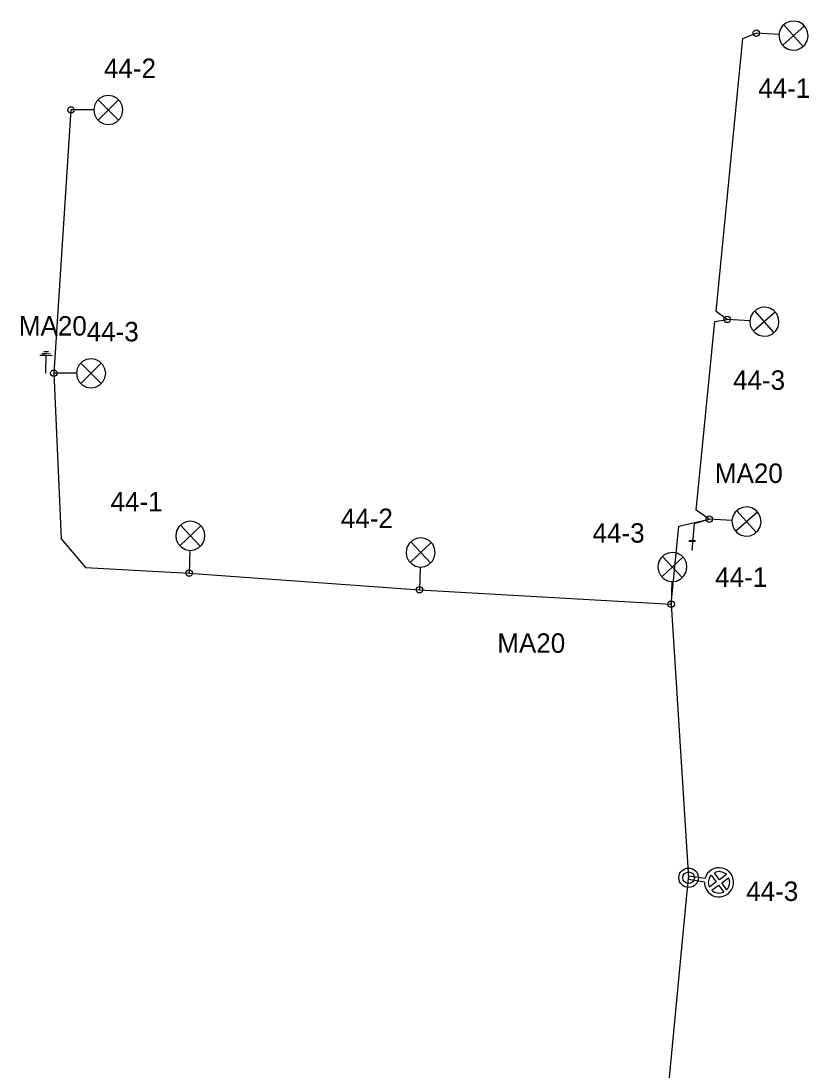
# Model space of a CAD drawing. Extents: x 25497851 to 25498523, y 6686544 to 6687372.
# Drawn here: x 25497852.5 to 25497974, y 6687207 to 6687368.9 of the extents above; entities that cross this region are included whole.
import ezdxf

# ---------------------------------------------------------------- set-up
doc = ezdxf.new("R2010")
doc.units = 0
for name, color, linetype in [('EL_CABLE_MAA', 7, 'Continuous'), ('KAAPELI', 7, 'Continuous'), ('KEYGWT_ANNOTATION', 7, 'Continuous'), ('Level 17', 7, 'Continuous'), ('Level 63', 7, 'Continuous'), ('PYLVAS', 7, 'Continuous'), ('Taso 1', 7, 'Continuous'), ('VALAISIN', 7, 'Continuous')]:
    doc.layers.add(name, color=color, linetype=linetype)

msp = doc.modelspace()

# ---------------------------------------------------------------- linework, layer by layer
at = {"layer": 'EL_CABLE_MAA'}
for points in [[(25497961.39, 6687322.89), (25497959.67, 6687324.13), (25497963.77, 6687366.17), (25497965.87, 6687367.01)], [(25497860.17, 6687355.18), (25497857.52, 6687314.58)], [(25497958.62, 6687292.08), (25497956.57, 6687293.5), (25497959.48, 6687322.57), (25497961.39, 6687322.89)], [(25497857.52, 6687314.58), (25497858.66, 6687289.03), (25497862.4, 6687284.66), (25497878.39, 6687283.78)], [(25497952.75, 6687278.97), (25497953.92, 6687291), (25497958.62, 6687292.08)], [(25497955.97, 6687287.26), (25497956.36, 6687291.42), (25497958.62, 6687292.08)], [(25497878.39, 6687283.78), (25497913.92, 6687281.21)], [(25497913.92, 6687281.21), (25497952.75, 6687278.97)], [(25497952.75, 6687278.97), (25497955.43, 6687236.8)]]:
    msp.add_lwpolyline(points, dxfattribs=at)
at = {"layer": 'KAAPELI'}
msp.add_line((25497951.39, 6687194.86), (25497955.43, 6687236.8), dxfattribs=at)
at = {"layer": 'Level 17'}
for points in [[(25497855.37, 6687317.37), (25497856.31, 6687317.36)], [(25497855.66, 6687317.62), (25497856.33, 6687317.61)], [(25497856.33, 6687317.87), (25497855.96, 6687317.88)], [(25497856.28, 6687314.62), (25497856.32, 6687317.35)], [(25497856.31, 6687317.36), (25497857.26, 6687317.34)], [(25497856.71, 6687317.87), (25497856.33, 6687317.87)], [(25497856.33, 6687317.61), (25497857, 6687317.6)]]:
    msp.add_lwpolyline(points, dxfattribs=at)
at = {"layer": 'PYLVAS'}
for radius in [1.5, 0.9]:
    msp.add_circle((25497955.43, 6687236.8), radius, dxfattribs=at)
at = {"layer": 'Taso 1'}
for p, q in [((25497973.27, 6687368.12), (25497969.94, 6687365.18)), ((25497973.08, 6687364.98), (25497970.14, 6687368.31)), ((25497969.36, 6687366.79), (25497965.87, 6687367.01)), ((25497867.49, 6687356.75), (25497864.35, 6687353.61)), ((25497867.49, 6687353.61), (25497864.35, 6687356.75)), ((25497863.67, 6687355.18), (25497860.17, 6687355.18)), ((25497968.79, 6687324), (25497965.46, 6687321.06)), ((25497968.6, 6687320.87), (25497965.66, 6687324.2)), ((25497964.88, 6687322.67), (25497961.39, 6687322.89)), ((25497864.84, 6687316.15), (25497861.7, 6687313)), ((25497864.84, 6687313), (25497861.7, 6687316.15)), ((25497861.02, 6687314.58), (25497857.52, 6687314.58)), ((25497966.03, 6687293.19), (25497962.7, 6687290.25)), ((25497965.83, 6687290.06), (25497962.89, 6687293.39)), ((25497962.12, 6687291.87), (25497958.62, 6687292.08)), ((25497880.19, 6687291.04), (25497876.95, 6687288)), ((25497877.05, 6687291.14), (25497880.1, 6687287.9)), ((25497915.72, 6687288.47), (25497912.48, 6687285.43)), ((25497912.58, 6687288.57), (25497915.62, 6687285.33)), ((25497955.49, 6687288.7), (25497956.46, 6687288.64)), ((25497955.5, 6687288.84), (25497956.47, 6687288.78)), ((25497878.5, 6687287.27), (25497878.39, 6687283.78)), ((25497954.55, 6687286.23), (25497951.31, 6687283.19)), ((25497951.41, 6687286.33), (25497954.45, 6687283.09)), ((25497914.03, 6687284.7), (25497913.92, 6687281.21)), ((25497952.86, 6687282.46), (25497952.75, 6687278.97))]:
    msp.add_line(p, q, dxfattribs=at)
for points in [[(25497973.85, 6687366.51), (25497973.79, 6687367.21), (25497973.51, 6687367.85), (25497973.04, 6687368.38), (25497972.43, 6687368.74), (25497971.75, 6687368.89), (25497971.05, 6687368.83), (25497970.4, 6687368.55), (25497969.87, 6687368.08), (25497969.52, 6687367.48), (25497969.36, 6687366.79), (25497969.43, 6687366.09), (25497969.71, 6687365.44), (25497970.17, 6687364.91), (25497970.78, 6687364.56), (25497971.47, 6687364.4), (25497972.17, 6687364.47), (25497972.81, 6687364.75), (25497973.34, 6687365.21), (25497973.7, 6687365.82)], [(25497868.17, 6687355.18), (25497868.06, 6687355.87), (25497867.74, 6687356.5), (25497867.24, 6687357), (25497866.62, 6687357.32), (25497865.92, 6687357.43), (25497865.23, 6687357.32), (25497864.6, 6687357), (25497864.1, 6687356.5), (25497863.78, 6687355.87), (25497863.67, 6687355.18), (25497863.78, 6687354.48), (25497864.1, 6687353.86), (25497864.6, 6687353.36), (25497865.23, 6687353.04), (25497865.92, 6687352.93), (25497866.62, 6687353.04), (25497867.24, 6687353.36), (25497867.74, 6687353.86), (25497868.06, 6687354.48)], [(25497969.37, 6687322.39), (25497969.3, 6687323.09), (25497969.02, 6687323.74), (25497968.56, 6687324.27), (25497967.95, 6687324.62), (25497967.27, 6687324.78), (25497966.57, 6687324.71), (25497965.92, 6687324.43), (25497965.39, 6687323.97), (25497965.03, 6687323.36), (25497964.88, 6687322.67), (25497964.95, 6687321.97), (25497965.23, 6687321.33), (25497965.69, 6687320.8), (25497966.3, 6687320.44), (25497966.98, 6687320.29), (25497967.68, 6687320.35), (25497968.33, 6687320.63), (25497968.86, 6687321.1), (25497969.22, 6687321.7)], [(25497865.52, 6687314.58), (25497865.41, 6687315.27), (25497865.09, 6687315.9), (25497864.59, 6687316.4), (25497863.96, 6687316.72), (25497863.27, 6687316.83), (25497862.57, 6687316.72), (25497861.95, 6687316.4), (25497861.45, 6687315.9), (25497861.13, 6687315.27), (25497861.02, 6687314.58), (25497861.13, 6687313.88), (25497861.45, 6687313.25), (25497861.95, 6687312.76), (25497862.57, 6687312.44), (25497863.27, 6687312.33), (25497863.96, 6687312.44), (25497864.59, 6687312.76), (25497865.09, 6687313.25), (25497865.41, 6687313.88)], [(25497966.61, 6687291.58), (25497966.54, 6687292.28), (25497966.26, 6687292.93), (25497965.8, 6687293.46), (25497965.19, 6687293.82), (25497964.5, 6687293.97), (25497963.8, 6687293.9), (25497963.16, 6687293.62), (25497962.63, 6687293.16), (25497962.27, 6687292.55), (25497962.12, 6687291.87), (25497962.18, 6687291.16), (25497962.46, 6687290.52), (25497962.93, 6687289.99), (25497963.53, 6687289.63), (25497964.22, 6687289.48), (25497964.92, 6687289.54), (25497965.57, 6687289.82), (25497966.09, 6687290.29), (25497966.45, 6687290.9)], [(25497878.65, 6687291.77), (25497877.95, 6687291.68), (25497877.31, 6687291.38), (25497876.8, 6687290.9), (25497876.46, 6687290.28), (25497876.33, 6687289.59), (25497876.41, 6687288.9), (25497876.71, 6687288.26), (25497877.2, 6687287.75), (25497877.81, 6687287.41), (25497878.5, 6687287.27), (25497879.2, 6687287.36), (25497879.84, 6687287.66), (25497880.35, 6687288.14), (25497880.69, 6687288.76), (25497880.82, 6687289.45), (25497880.74, 6687290.15), (25497880.44, 6687290.79), (25497879.95, 6687291.3), (25497879.34, 6687291.64)], [(25497914.17, 6687289.2), (25497913.47, 6687289.11), (25497912.83, 6687288.81), (25497912.32, 6687288.33), (25497911.98, 6687287.71), (25497911.85, 6687287.02), (25497911.94, 6687286.33), (25497912.24, 6687285.69), (25497912.72, 6687285.18), (25497913.33, 6687284.84), (25497914.03, 6687284.7), (25497914.72, 6687284.79), (25497915.36, 6687285.09), (25497915.87, 6687285.57), (25497916.21, 6687286.19), (25497916.35, 6687286.88), (25497916.26, 6687287.58), (25497915.96, 6687288.22), (25497915.48, 6687288.73), (25497914.86, 6687289.07)], [(25497953, 6687286.96), (25497952.3, 6687286.87), (25497951.66, 6687286.57), (25497951.15, 6687286.09), (25497950.81, 6687285.47), (25497950.68, 6687284.78), (25497950.77, 6687284.08), (25497951.07, 6687283.45), (25497951.55, 6687282.93), (25497952.17, 6687282.6), (25497952.86, 6687282.46), (25497953.56, 6687282.55), (25497954.19, 6687282.85), (25497954.71, 6687283.33), (25497955.05, 6687283.95), (25497955.18, 6687284.64), (25497955.09, 6687285.34), (25497954.79, 6687285.98), (25497954.31, 6687286.49), (25497953.69, 6687286.83)]]:
    msp.add_lwpolyline(points, close=True, dxfattribs=at)
for centre in [(25497965.87, 6687367.01), (25497860.17, 6687355.18), (25497961.39, 6687322.89), (25497857.52, 6687314.58), (25497958.62, 6687292.08), (25497878.39, 6687283.78), (25497913.92, 6687281.21), (25497952.75, 6687278.97)]:
    msp.add_circle(centre, 0.5, dxfattribs=at)
at = {"layer": 'VALAISIN'}
for p, q in [((25497955.39, 6687236.51), (25497955.48, 6687237.1)), ((25497957.87, 6687236.13), (25497955.39, 6687236.51)), ((25497955.48, 6687237.1), (25497957.96, 6687236.72)), ((25497958.92, 6687237.22), (25497959.7, 6687236.15)), ((25497960.18, 6687236.5), (25497959.4, 6687237.57)), ((25497961.25, 6687237.29), (25497960.18, 6687236.5)), ((25497960.54, 6687236.02), (25497961.6, 6687236.8)), ((25497959.7, 6687236.15), (25497958.63, 6687235.37)), ((25497958.99, 6687234.88), (25497960.05, 6687235.67)), ((25497960.05, 6687235.67), (25497960.84, 6687234.6)), ((25497961.32, 6687234.95), (25497960.54, 6687236.02))]:
    msp.add_line(p, q, dxfattribs=at)
for radius, start, end in [(2.25, 351.2726, 163.6103), (1.65, 136.7482, 171.2726), (1.65, 46.7482, 115.7969), (1.65, 351.2726, 25.7969), (2.25, 178.9348, 351.2726), (1.65, 171.2726, 205.7969), (1.65, 226.7482, 295.7969), (1.65, 316.7482, 351.2726)]:
    msp.add_arc((25497960.12, 6687236.09), radius, start, end, dxfattribs=at)

# ---------------------------------------------------------------- texts
at = {"layer": 'KEYGWT_ANNOTATION'}
for s, p in [('44-2', (25497865.25, 6687360.1)), ('44-1', (25497966.17, 6687357.03)), ('MA20', (25497852.13, 6687320.39)), ('44-3', (25497862.59, 6687319.5)), ('44-3', (25497962.28, 6687312.03)), ('MA20', (25497959.48, 6687297.67)), ('44-1', (25497866.26, 6687293.28)), ('44-2', (25497901.79, 6687290.71)), ('44-3', (25497940.62, 6687288.47)), ('44-1', (25497959.52, 6687281.65)), ('MA20', (25497925.92, 6687271.48)), ('44-3', (25497964.31, 6687233.22))]:
    msp.add_text(s, height=3, dxfattribs=at).set_placement(p)
at = {"layer": 'Level 63'}
msp.add_text('(C) KEYPRO 2000', height=0.0001, rotation=179.1, dxfattribs=at).set_placement((25497856.71, 6687317.87))

doc.saveas('drawing.dxf')
